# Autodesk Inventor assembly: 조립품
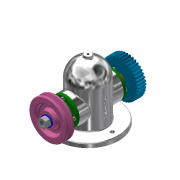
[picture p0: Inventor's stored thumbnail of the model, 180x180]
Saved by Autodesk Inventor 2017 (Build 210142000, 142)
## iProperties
Created: 2019-11
Part Number: 조립품
Document SubType Name: Assembly
Designer: 1-11-lg
Author: 1-11-lg
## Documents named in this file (14)
- C:\Users\1-11-lg\Desktop\491104V1002\조립품.iam
- C:\Users\1-11-lg\Desktop\491104V1002\본체.ipt
- C:\Users\1-11-lg\Desktop\491104V1002\V-벨트풀리.ipt
- V-벨트풀리.ipt
- C:\Users\1-11-lg\Desktop\491104V1002\너트 M12x1.25.ipt
- C:\Users\1-11-lg\Desktop\491104V1002\베어링 6203.ipt
- C:\Users\1-11-lg\Desktop\491104V1002\볼트 M4.ipt
- C:\Users\1-11-lg\Desktop\491104V1002\부시.ipt
- C:\Users\1-11-lg\Desktop\491104V1002\스퍼기어.ipt
- C:\Users\1-11-lg\Desktop\491104V1002\오일 실 26 38 8.ipt
- C:\Users\1-11-lg\Desktop\491104V1002\와셔 12x24.ipt
- C:\Users\1-11-lg\Desktop\491104V1002\축.ipt
- C:\Users\1-11-lg\Desktop\491104V1002\커버.ipt
- C:\Users\1-11-lg\Desktop\491104V1002\키 5x5x12.ipt
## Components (1 placed, 1 different names)
1. V-벨트풀리:1 — Mate:3, Mate:4, Mate:6, Mate:11
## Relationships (4: Mate 4)
- Mate:3: V-벨트풀리:1
- Mate:4: V-벨트풀리:1
- Mate:6: V-벨트풀리:1
- Mate:11: V-벨트풀리:1
